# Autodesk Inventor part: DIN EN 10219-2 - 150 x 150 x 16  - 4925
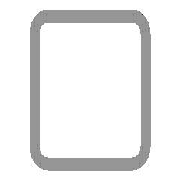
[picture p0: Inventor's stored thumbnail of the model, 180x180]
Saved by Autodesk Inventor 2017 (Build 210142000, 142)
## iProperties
IsCustomPart: 1
Created: 2016-02
Part Number: DIN EN 10219-2 - 150 x 150 x 16  - 4925
Material: Steel, Mild
Description: Cold formed welded structural hollow sections of non-alloy and fine grain structural steel
Document SubType Name: Modeling
Standard: DIN
Designer: iusti
Standard Revision: 2006-07
Standards Organization: DIN
Language: en-US
Size Designation: 150 x 150 x 16
Categories: <MemberInstance><Categories><Category DisplayName="Structural Shapes" InternalName="089c4875-fa83-4c05-b084-43b9cc11f5ed" Mnemonic="GRDR"><CategoryParameter Dis
Stock Number: 150 x 150 x 16
Density: 7.85 g/cm^3
Appearance: Semi-Polished
Mass: 289079 g
Surface Area: 46181.3 cm^2
Volume: 36825.4 cm^3
_CCFamilyMember: 76
_CCFamilyDisplayName: DIN EN 10219-2 (Square Hollow Section - Cold Formed) - Cold formed welded structural hollow sections of non-alloy and fine grain structural steel
_FrameMemberDoc: Frame Member File
_Version: 15.0.0
_GetPNFromCC: 1
G_L: 4925.000 mm
G_W: 150.000 mm
G_H: 150.000 mm
+0D5BCBA2-F1B2-4388-A824-2414ADB6311C+CUTDETAIL1: Cut
Author: iusti
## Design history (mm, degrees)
node "Start plane"
node "End plane"
sketch "Sketch"
  geometry: L1 (-75, -27)-(-75, 27); L2 (-27, 75)-(27, 75); L3 (75, 27)-(75, -27); L4 (27, -75)-(-27, -75); L5 (-27, 59)-(27, 59); L6 (59, 27)-(59, -27); L7 (27, -59)-(-27, -59); L8 (-59, -27)-(-59, 27); L9 (0, 118.918)-(0, -118.918) reference; L10 (-118.918, 0)-(118.918, 0) reference; A1 r 48 centre (-27, -27) between (-75, -27) and (-27, -75); A2 r 48 centre (-27, 27) between (-27, 75) and (-75, 27); A3 r 48 centre (27, 27) between (75, 27) and (27, 75); A4 r 48 centre (27, -27) between (27, -75) and (75, -27); A5 r 32 centre (-27, 27) between (-27, 59) and (-59, 27); A6 r 32 centre (27, 27) between (59, 27) and (27, 59); A7 r 32 centre (27, -27) between (27, -59) and (59, -27); A8 r 32 centre (-27, -27) between (-59, -27) and (-27, -59)
  constraints: 16 end point, 16 point on circle, 8 centre point, 8 tangent, 4 parallel, 3 equal radius, 2 perpendicular, 7 other
  dimensions: "d7" = 48 radius of A1 (= G_IR); "d10" = 150 distance between parallel lines of L2 L4 (= G_H); "d11" = 150 distance between parallel lines of L1 L3 (= G_W); "d12" = 16 distance between parallel lines of L3 L6 (= G_T); "d15" = 75 distance between parallel lines of L2 L10 (= 0.5 x d10); "d16" = 75 distance between parallel lines of L9 L3 (= 0.5 x d11)
extrude "Body" new body sketch "Sketch" stored distance "d3" = 4925 (= G_L); taper "d4" = 0 deg
node "Driven Length"
  sketch "Sketch3"
    geometry: L1 (0, 0)-(10, 0) reference
    constraints: 2 end point, 1 horizontal
  workplane "Work Plane3"
  sketch "Sketch4"
    geometry: L1 (-2, 75)-(12, 75) reference; L2 (-2, 5000)-(12, 5000) reference
    dimensions: "d18" = 4925 distance between parallel lines of L1 L2 (derived)
workplane "Work Plane4"
split "Split1"
body "Solid1"
other parameters: "G_W" = 150 [user parameter; used in 1 equation term], "G_H" = 150 [user parameter; used in 1 equation term], "G_T" = 16 [user parameter; used in 1 equation term], "G_IR" = 48 [user parameter; used in 1 equation term], "G_L" = 4925 (= d18) [user parameter; used in 1 equation term], "G_OFFSET_START" = -75 [user parameter; used in 1 equation term], "G_OFFSET_END" = 0 [user parameter; used in 1 equation term], "d13" = 75 (= -G_OFFSET_START), "d17" = 90 deg
